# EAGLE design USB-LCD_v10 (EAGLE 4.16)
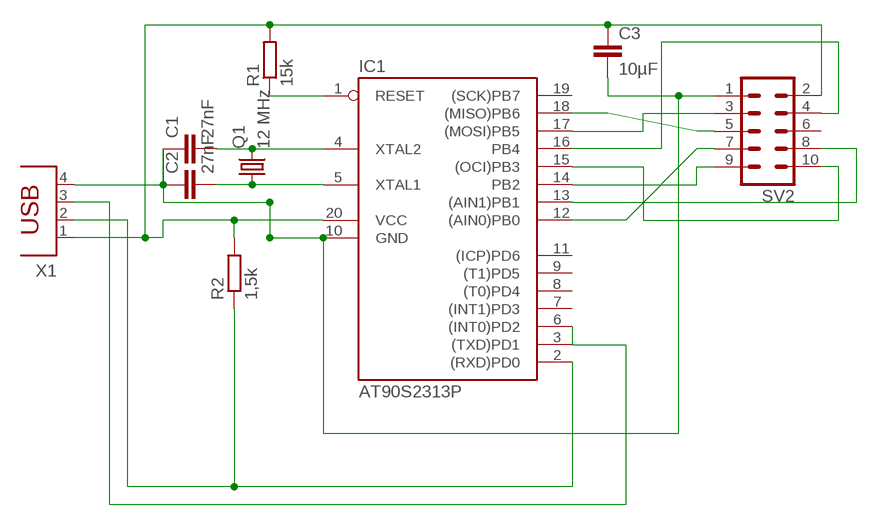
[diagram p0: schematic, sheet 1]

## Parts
C1  27nF  C2,5-3  [C2.5-3]
C2  27nF  C2,5-3  [C2.5-3]
C3  10µF  C2.5/6  [C2.5-6]
IC1  AT90S2313P  [DIL20]
Q1  12 MHz  CRYSTALHC49S  [HC49/S]
R1  15k  R-EU_0207/10  [0207/10]
R2  1,5k  R-EU_0207/10  [0207/10]
SV2  ML10  [ML10]
X1  PN61729  [PN61729]

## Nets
N$1: IC1.3((TXD)PD1) IC1.6((INT0)PD2) X1.3
N$2: IC1.2((RXD)PD0) R2.1 X1.2
N$3: IC1.16(PB4) SV2.4
N$4: C1.1 C2.1 C3.2 IC1.10(GND) SV2.1 X1.4
N$5: C1.2 IC1.4(XTAL2) Q1.2
N$6: C2.2 IC1.5(XTAL1) Q1.1
N$7: C3.1 IC1.20(VCC) R1.2 R2.2 SV2.2 X1.1
N$8: IC1.17((MOSI)PB5) SV2.3
N$9: IC1.18((MISO)PB6) SV2.5
N$10: IC1.13((AIN1)PB1) SV2.8
N$11: IC1.12((AIN0)PB0) SV2.7
N$12: IC1.14(PB2) SV2.9
N$13: IC1.15((OCI)PB3) SV2.10
N$16: IC1.1(RESET) R1.1
Unconnected: IC1.7((INT1)PD3) IC1.8((T0)PD4) IC1.9((T1)PD5) IC1.11((ICP)PD6) IC1.19((SCK)PB7) SV2.6

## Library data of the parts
C1-C3 = capacitor-wima:C: CAPACITOR
IC1 = atmel:AT90S2313: MICROCONTROLLER 2 Kbytes FLASH 128 bytes SRAM 128 bytes EEPROM UART
Q1 = crystal:CRYSTAL: CRYSTAL
R1 R2 = rcl:R-EU_: RESISTOR, European symbol
SV2 = con-harting-ml:ML10: HARTING
X1 = con-berg:PN61729: BERG USB connector

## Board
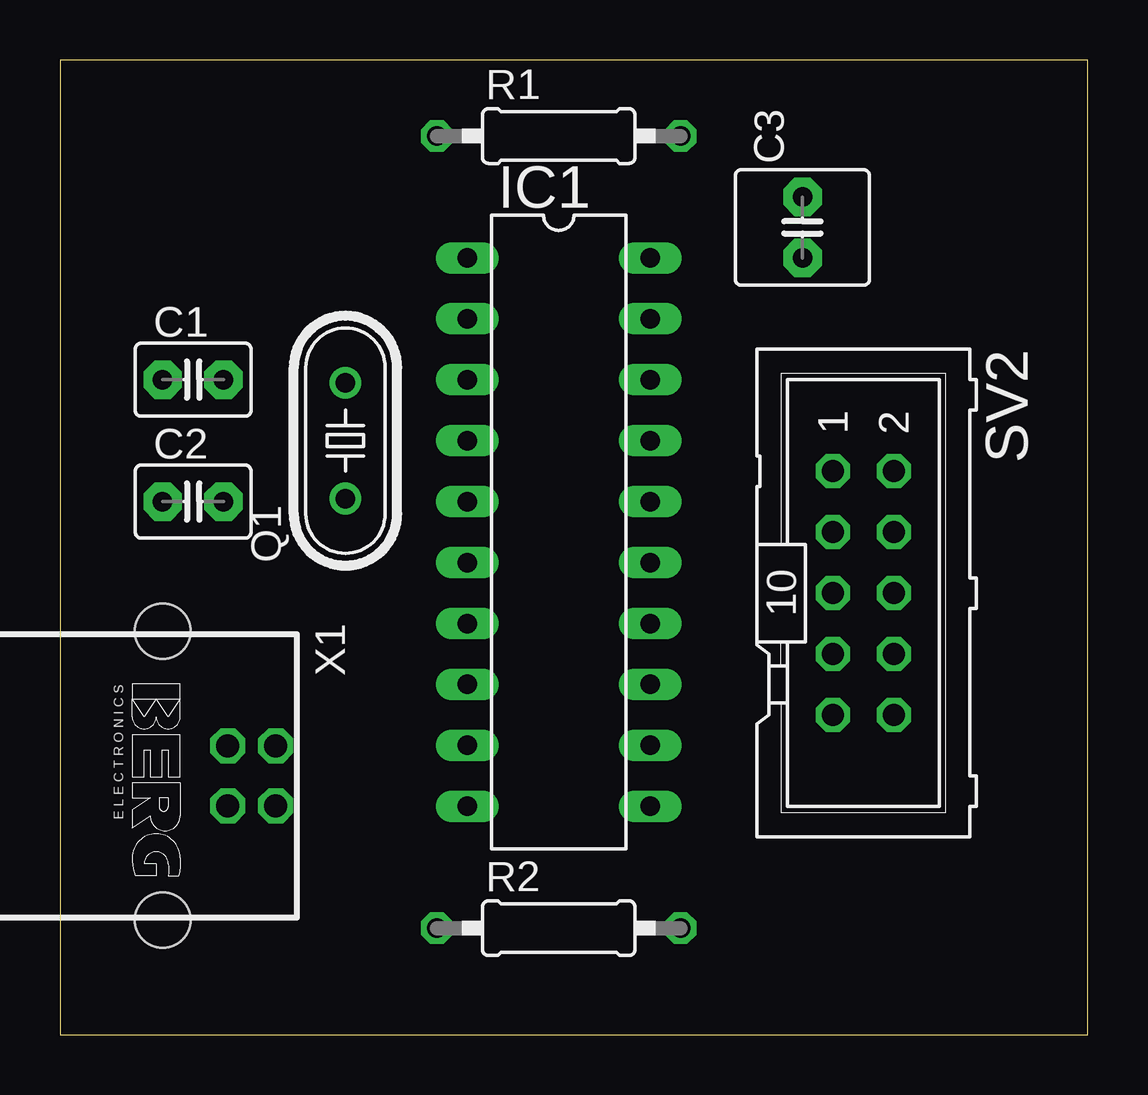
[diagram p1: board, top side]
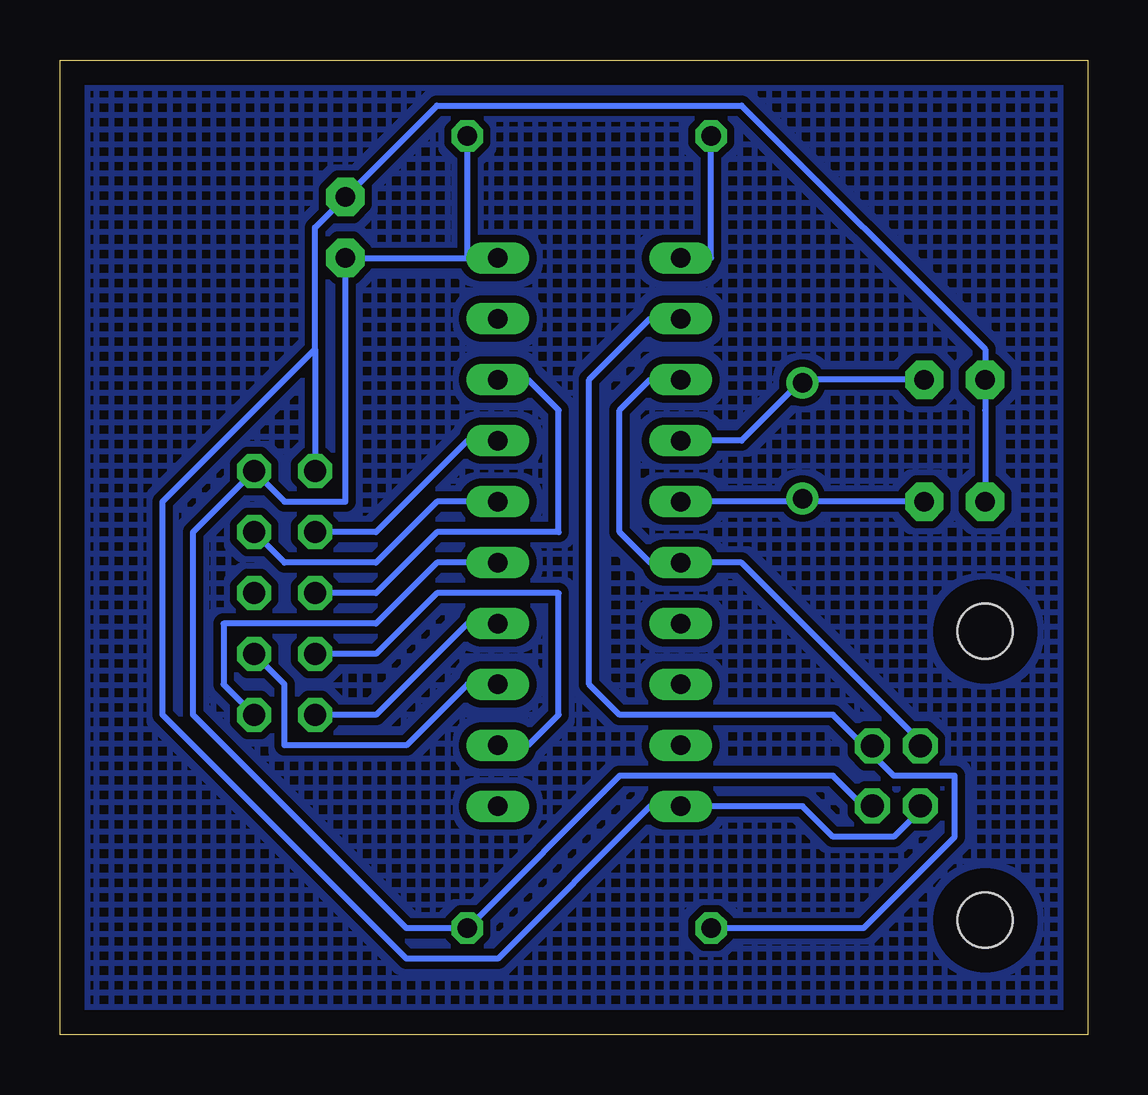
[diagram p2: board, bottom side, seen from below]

Size 42.85 x 40.63 mm. Coordinates in mm from the lower left corner, seen from the top.
Outline: 0,0 42.85,0 42.85,40.63 0,40.63 0,0
Copper layers (1*16): Top 0.035mm / dielectric 1.5mm / Bottom 0.035mm
Design rules "default": minimum track width 10mil, minimum drill 24mil, track to track 8mil, track to pad 8mil, pad to pad 8mil, via to via 8mil, smd to smd 8mil, copper to edge 40mil, drill to drill 8mil, minimum pad ring 10mil, minimum via ring 8mil, stop-mask expansion 4mil, vias tented up to drill 0mil, thermal gap 10mil

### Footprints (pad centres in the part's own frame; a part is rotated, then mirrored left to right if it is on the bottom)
C2.5-3 = drill 0.813 pad 1.6 octagon: 1 -1.27,0; 2 1.27,0
C2.5-6 = drill 0.813 pad 1.6 octagon: 1 -1.27,0; 2 1.27,0
DIL20 = drill 0.813 long: 1 -11.43,-3.81; 2 -8.89,-3.81; 3 -6.35,-3.81; 4 -3.81,-3.81; 5 -1.27,-3.81; 6 1.27,-3.81; 7 3.81,-3.81; 8 6.35,-3.81; 9 8.89,-3.81; 10 11.43,-3.81; 11 11.43,3.81; 12 8.89,3.81; 13 6.35,3.81; 14 3.81,3.81; 15 1.27,3.81; 16 -1.27,3.81; 17 -3.81,3.81; 18 -6.35,3.81; 19 -8.89,3.81; 20 -11.43,3.81
HC49/S = drill 0.813 round: 1 -2.413,0; 2 2.413,0
0207/10 = drill 0.813 octagon: 1 -5.08,0; 2 5.08,0
ML10 = drill 0.914 octagon: 1 -5.08,-1.27; 2 -5.08,1.27; 3 -2.54,-1.27; 4 -2.54,1.27; 5 0,-1.27; 6 0,1.27; 7 2.54,-1.27; 8 2.54,1.27; 9 5.08,-1.27; 10 5.08,1.27
PN61729 = drill 0.95 octagon: 1 1.25,4.71; 2 -1.25,4.71; 3 -1.25,2.71; 4 1.25,2.71 | hole 2.3: -6.02,0; 6.02,0

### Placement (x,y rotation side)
C1  5.55,27.3 0 top
C2  5.55,22.22 0 top
C3  30.95,33.65 90 top
IC1  20.79,20.95 270 top
Q1  11.9,24.76 90 top
R1  20.79,37.46 0 top
R2  20.79,4.44 0 top
SV2  33.49,18.41 270 top
X1  4.28,10.79 270 top

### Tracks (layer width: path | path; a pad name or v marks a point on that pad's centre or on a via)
N$1
  Bottom 0.254: IC1.3 18.25,27.3 19.52,26.03 19.52,20.95 18.25,19.68 IC1.6 14.44,19.68 6.82,12.06 X1.3
N$2
  Bottom 0.254: R2.1 9.36,4.44 5.55,8.25 5.55,10.79 8.09,10.79 9.36,12.06 | 9.36,12.06 10.63,13.33 19.52,13.33 20.79,14.6 20.79,27.3 18.25,29.84 IC1.2 | 9.36,12.06 X1.2
N$3
  Bottom 0.254: SV2.4 33.49,19.68 29.68,19.68 27.14,22.22 IC1.16
N$4
  Bottom 0.254: X1.4 6.82,9.52 8.09,8.25 10.63,8.25 11.9,9.52 IC1.10 18.25,9.52 24.6,3.17 28.41,3.17 38.57,13.33 38.57,22.22 32.22,28.57 | C2.1 4.28,26.03 C1.1 4.28,28.57 14.44,38.73 27.14,38.73 C3.2 32.22,33.65 32.22,28.57 | 32.22,28.57 SV2.1
N$5
  Bottom 0.254: 11.9,27.3 Q1.2 | 11.9,27.3 14.44,24.76 IC1.4 | C1.2 11.9,27.3
N$6
  Bottom 0.254: 11.9,22.22 IC1.5 | C2.2 11.9,22.22 | 11.9,22.22 Q1.1
N$7
  Bottom 0.254: X1.1 9.36,9.52 10.63,10.79 19.52,10.79 R2.2 28.41,4.44 37.3,13.33 37.3,20.95 SV2.2 33.49,22.22 30.95,22.22 C3.1 25.87,32.38 | 25.87,32.38 R1.2 | 25.87,32.38 IC1.20
N$8
  Bottom 0.254: SV2.3 29.68,20.95 25.87,24.76 IC1.17
N$9
  Bottom 0.254: SV2.5 29.68,18.41 27.14,20.95 22.06,20.95 22.06,26.03 23.33,27.3 IC1.18
N$10
  Bottom 0.254: SV2.8 33.49,14.6 33.49,12.06 28.41,12.06 25.87,14.6 IC1.13
N$11
  Bottom 0.254: SV2.7 29.68,15.87 27.14,18.41 22.06,18.41 22.06,13.33 23.33,12.06 IC1.12
N$12
  Bottom 0.254: SV2.9 29.68,13.33 25.87,17.14 IC1.14
N$13
  Bottom 0.254: SV2.10 36.03,14.6 36.03,17.14 29.68,17.14 27.14,19.68 IC1.15
N$14
  pour Bottom (isolate 0.305, hatched): -0.8,41.27 43.65,41.27 43.65,-0.64 -0.8,-0.64
N$16
  Bottom 0.254: R1.1 15.71,32.38 IC1.1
